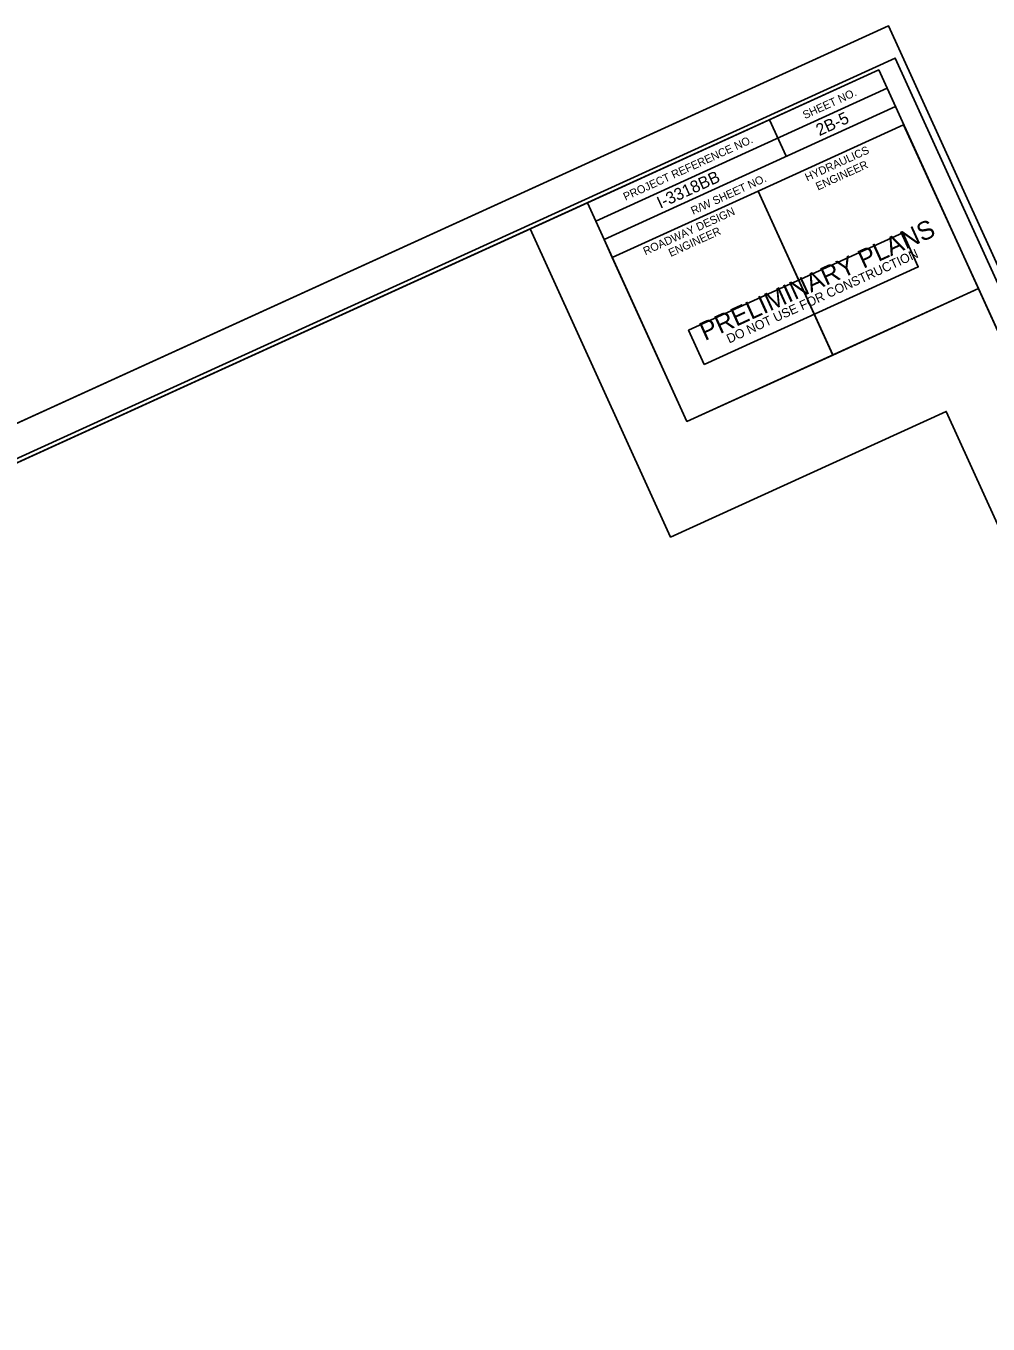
# Model space of a CAD drawing. Extents: x 2245059 to 2247045, y 661437 to 663204.
# Drawn here: x 2246052 to 2246653, y 662321 to 663131 of the extents above; entities that cross this region are included whole.
import ezdxf

# ---------------------------------------------------------------- set-up
doc = ezdxf.new("R2010")
doc.units = 0
for name, color, linetype in [('Sheet Clip Boundary CELL', 7, 'Continuous'), ('Sheet Cutting Line CELL', 7, 'Continuous'), ('Sheet Data Field CELL', 7, 'Continuous'), ('Sheet Plan CELL', 7, 'Continuous'), ('Sheet Plot Border Inside CELL', 7, 'Continuous'), ('Sheet Plot Border Outside CELL', 7, 'Continuous'), ('Sheet Sticker Preliminary CELL', 7, 'Continuous')]:
    doc.layers.add(name, color=color, linetype=linetype)

msp = doc.modelspace()

# ---------------------------------------------------------------- linework, layer by layer
at = {"layer": 'Sheet Clip Boundary CELL'}
msp.add_lwpolyline([(2245700.34, 661547.14), (2246974.32, 662127.67), (2246626.62, 662890.7), (2246454.4, 662812.22), (2246366.7, 663004.67), (2245264.95, 662502.62)], close=True, dxfattribs=at)
at = {"layer": 'Sheet Cutting Line CELL'}
msp.add_line((2246590.57, 663131.39), (2245058.62, 662433.31), dxfattribs=at)
at = {"layer": 'Sheet Plan CELL'}
for p, q in [((2246407.57, 663009.51), (2246589.62, 663092.46)), ((2246412.78, 662998.11), (2246594.8, 663081.08)), ((2246412.78, 662998.11), (2246594.8, 663081.08)), ((2246516.17, 663072.71), (2246526.58, 663049.98)), ((2246509, 663028.23), (2246555.65, 662925.9)), ((2246412.78, 662998.11), (2246417.96, 662986.75))]:
    msp.add_line(p, q, dxfattribs=at)
for points in [[(2246584.45, 663103.89), (2245219.45, 662481.89), (2245654.84, 661526.41), (2247019.82, 662148.41)], [(2246402.38, 663020.94), (2246584.45, 663103.89), (2246594.8, 663081.08), (2246412.78, 662998.11)], [(2246509, 663028.23), (2246599.98, 663069.71), (2246646.65, 662967.33), (2246555.66, 662925.85)], [(2246417.96, 662986.75), (2246509, 663028.23), (2246555.66, 662925.85), (2246464.61, 662884.39)], [(2245654.84, 661526.41), (2245219.44, 662481.85), (2246402.38, 663020.94), (2246464.61, 662884.39), (2246646.65, 662967.33), (2247019.82, 662148.41)]]:
    msp.add_lwpolyline(points, close=True, dxfattribs=at)
at = {"layer": 'Sheet Plot Border Inside CELL'}
msp.add_lwpolyline([(2245516.21, 661460.48), (2247032.22, 662151.31), (2246594.77, 663111.33), (2245078.75, 662420.5)], close=True, dxfattribs=at)
at = {"layer": 'Sheet Plot Border Outside CELL'}
msp.add_lwpolyline([(2245512.68, 661436.89), (2247044.62, 662134.97), (2246590.57, 663131.39), (2245058.62, 662433.31)], close=True, dxfattribs=at)
at = {"layer": 'Sheet Sticker Preliminary CELL'}
msp.add_lwpolyline([(2246475.38, 662919.93), (2246465.63, 662941.32), (2246599.4, 663002.27), (2246609.15, 662980.89)], close=True, dxfattribs=at)

# ---------------------------------------------------------------- texts
at = {"layer": 'Sheet Data Field CELL'}
for s, p in [('2B-5', (2246547.29, 663062.51)), ('I-3318BB', (2246447.92, 663017.16))]:
    msp.add_text(s, height=7.5, rotation=24.49795, dxfattribs=at).set_placement(p)
at = {"layer": 'Sheet Plan CELL'}
for s, height, p in [('SHEET NO.', 5, (2246538.32, 663073.17)), ('PROJECT REFERENCE NO.', 5.0001, (2246426.2, 663022.21)), ('HYDRAULICS', 5, (2246539.74, 663034.25)), ('ENGINEER', 5, (2246546.46, 663028.56)), ('R/W SHEET NO.', 5.0001, (2246468.46, 663013.39)), ('ROADWAY DESIGN', 5.0001, (2246438.62, 662988.14)), ('ENGINEER', 5, (2246454.47, 662987.08))]:
    msp.add_text(s, height=height, rotation=24.49795, dxfattribs=at).set_placement(p)
at = {"layer": 'Sheet Sticker Preliminary CELL'}
for s, height, p in [('PRELIMINARY PLANS', 11.52, (2246475.84, 662934.59)), ('DO NOT USE FOR CONSTRUCTION', 5.76, (2246490.95, 662933.02))]:
    msp.add_text(s, height=height, rotation=24.49794, dxfattribs=at).set_placement(p)

doc.saveas('drawing.dxf')
